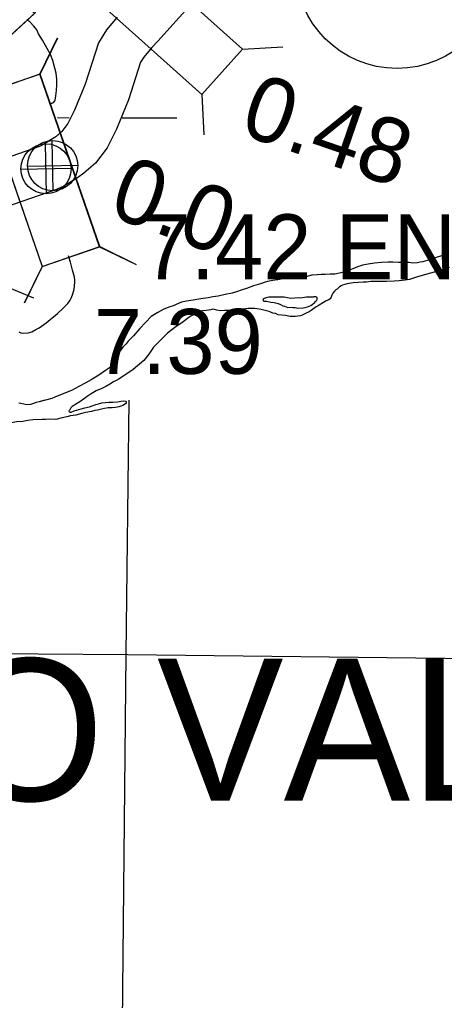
# Model space of a CAD drawing. Extents: x 369523 to 838377, y 495025 to 936819.
# Drawn here: x 596255 to 601784, y 797650 to 810419 of the extents above; entities that cross this region are included whole.
import ezdxf

# ---------------------------------------------------------------- set-up
doc = ezdxf.new("R2010")
doc.units = 0
for name, color, linetype in [('DSN_BRDG_Annotation', 7, 'Continuous'), ('DSN_DRFT_Common-Annotations', 7, 'Continuous'), ('DSN_DRFT_Common-Line', 7, 'Continuous'), ('DSN_DRFT_Junk-No-Plot', 7, 'Continuous'), ('Level 10', 7, 'Continuous'), ('Level 11', 7, 'Continuous'), ('Level 21', 7, 'Continuous'), ('Level 22', 7, 'Continuous'), ('Level 6', 7, 'Continuous')]:
    doc.layers.add(name, color=color, linetype=linetype)

msp = doc.modelspace()

# ---------------------------------------------------------------- linework, layer by layer
at = {"layer": 'DSN_DRFT_Common-Annotations'}
for p, q in [((596606, 808152), (596591, 808803)), ((596693, 808192), (596678, 808843)), ((596360, 808510), (597011, 808525)), ((596273, 808470), (596924, 808485))]:
    msp.add_line(p, q, dxfattribs=at)
for centre in [(596599, 808477), (596685, 808518)]:
    msp.add_circle(centre, 326, dxfattribs=at)
at = {"layer": 'DSN_DRFT_Common-Line'}
msp.add_circle((601167, 811103), 1320, dxfattribs=at)
at = {"layer": 'Level 10'}
for points in [[(601813, 807366), (601585, 807291), (601503, 807266), (601469, 807260), (601435, 807252), (601371, 807248), (601319, 807255), (601281, 807257), (601239, 807257), (601181, 807259), (601112, 807262), (601052, 807260), (600966, 807259), (600872, 807249), (600792, 807236), (600718, 807222), (600708, 807220)], [(600708, 807220), (600652, 807199), (600592, 807173), (600550, 807155), (600490, 807136), (600420, 807118), (600358, 807106), (600298, 807103), (600232, 807101), (600178, 807099), (600130, 807098), (600065, 807092), (600055, 807090), (599997, 807073), (599931, 807061), (599881, 807061), (599857, 807063), (599813, 807064), (599767, 807060), (599735, 807056), (599683, 807046), (599615, 807033), (599553, 807021), (599483, 807010), (599449, 807000), (599391, 806980), (599301, 806951), (599207, 806917), (599139, 806896), (599089, 806878), (599023, 806858), (598931, 806839), (598839, 806819), (598769, 806808), (598711, 806798), (598615, 806783), (598516, 806767), (598426, 806754), (598360, 806742), (598252, 806693), (598196, 806675), (598125, 806646), (598055, 806608), (597969, 806553), (597821, 806397), (597736, 806302), (597670, 806232), (597642, 806200), (597597, 806153), (597551, 806089), (597519, 806033), (597472, 805953), (597436, 805893), (597372, 805850), (597288, 805792), (597188, 805731), (597109, 805687), (597027, 805642), (596929, 805592), (596811, 805541), (596715, 805502), (596673, 805488), (596511, 805445), (596471, 805433), (596437, 805421), (596397, 805409), (596347, 805406), (596309, 805412), (596271, 805422), (596243, 805426)], [(601844, 807193), (601700, 807142), (601554, 807105), (601420, 807064), (601328, 807036), (601274, 807025), (601196, 807019), (601130, 807012), (601032, 807008), (600910, 807011), (600825, 807009), (600769, 807002), (600727, 807000), (600595, 806993), (600517, 806981), (600457, 806960), (600441, 806954), (600419, 806938), (600387, 806910), (600371, 806900), (600353, 806884), (600333, 806858), (600320, 806830), (600310, 806804), (600298, 806783), (600278, 806773), (600246, 806759), (600232, 806749), (600132, 806690), (600114, 806680), (600050, 806634), (600024, 806616), (599984, 806596), (599934, 806573), (599909, 806563), (599840, 806553), (599778, 806556), (599716, 806566), (599622, 806577), (599584, 806591), (599552, 806599), (599505, 806617), (599467, 806628), (599399, 806646), (599315, 806658)], [(599699, 806804), (599524, 806807), (599498, 806805), (599464, 806798), (599450, 806794), (599438, 806790), (599422, 806780), (599424, 806766), (599426, 806756), (599438, 806752), (599468, 806752), (599525, 806741), (599569, 806737), (599621, 806723), (599651, 806708), (599681, 806694), (599701, 806688), (599723, 806680), (599745, 806672)], [(599745, 806672), (599788, 806674), (599812, 806673), (599842, 806669), (599876, 806663), (599946, 806665), (599970, 806670), (600002, 806680), (600046, 806698), (600062, 806710), (600068, 806714), (600092, 806732), (600108, 806748), (600114, 806760), (600122, 806764), (600128, 806778), (600130, 806784), (600129, 806796), (600127, 806802), (600111, 806810), (600099, 806808), (600083, 806808), (600077, 806806), (600033, 806804), (599991, 806804), (599909, 806793), (599881, 806795), (599785, 806790), (599699, 806804)], [(599315, 806658), (599229, 806659), (599160, 806651), (599056, 806640), (598974, 806633), (598922, 806631), (598870, 806627), (598820, 806637), (598792, 806646), (598768, 806650), (598744, 806642), (598682, 806634), (598634, 806629), (598618, 806625), (598544, 806595), (598502, 806569), (598482, 806559), (598456, 806540), (598386, 806486), (598314, 806438), (598276, 806411), (598179, 806337), (598097, 806256), (597997, 806156), (597938, 806064), (597872, 805979), (597735, 805864), (597545, 805737), (597479, 805703), (597431, 805671), (597377, 805644), (597325, 805618), (597252, 805588), (597186, 805549), (597134, 805511), (597070, 805465), (597038, 805442), (596988, 805414), (596962, 805394), (596940, 805380), (596922, 805364), (596916, 805354), (596908, 805340), (596900, 805330), (596896, 805324), (596901, 805318), (596903, 805312), (596907, 805310), (596913, 805308), (596927, 805310), (596963, 805324), (597055, 805351), (597105, 805363), (597163, 805379), (597201, 805392), (597247, 805410), (597281, 805418), (597325, 805428), (597375, 805435), (597415, 805439), (597467, 805439), (597529, 805445), (597573, 805452), (597613, 805454), (597637, 805452), (597643, 805446), (597643, 805432), (597635, 805418), (597599, 805396), (597547, 805376), (597505, 805369), (597459, 805365), (597407, 805363), (597361, 805355), (597319, 805346), (597269, 805336), (597235, 805328), (597191, 805319), (597119, 805305), (597067, 805289), (596989, 805270), (596919, 805262), (596871, 805248), (596811, 805233), (596727, 805215), (596649, 805216), (596549, 805212), (596428, 805209), (596360, 805201), (596298, 805188), (596216, 805184)], [(596582, 805464), (596511, 805445), (596471, 805433), (596437, 805421), (596397, 805409), (596347, 805406), (596309, 805412), (596271, 805422), (596243, 805426)], [(596590, 805214), (596549, 805212), (596428, 805209), (596360, 805201), (596298, 805188), (596216, 805184), (596088, 805155), (595936, 805102), (595810, 805057), (595758, 805049), (595660, 805034), (595610, 805024), (595476, 805001), (595384, 804975), (595308, 804950), (595216, 804922)]]:
    msp.add_lwpolyline(points, dxfattribs=at)
at = {"layer": 'Level 11'}
for points in [[(598608, 810757), (598054, 810138), (597976, 810054), (597872, 809931), (597830, 809863), (597673, 809373), (597516, 808992), (597394, 808748), (597243, 808550), (597092, 808418), (597008, 808361), (596831, 808252), (596735, 808209), (596634, 808174)], [(597526, 810451), (597385, 810284), (597281, 810116), (597109, 809579), (596970, 809241), (596882, 809066), (596803, 808962), (596725, 808895), (596681, 808865), (596549, 808783), (596513, 808767), (596438, 808741)], [(596787, 808948), (596725, 808895), (596681, 808865), (596549, 808783), (596513, 808767), (595404, 808383), (594517, 808019)], [(596987, 808348), (596831, 808252), (596735, 808209), (595616, 807822), (594745, 807464)]]:
    msp.add_lwpolyline(points, dxfattribs=at)
at = {"layer": 'Level 21'}
for p, q in [((596518, 809709), (596749, 810183)), ((596521, 809709), (596752, 810184)), ((599154, 810036), (599681, 810065)), ((598626, 809446), (598655, 808919)), ((597295, 807463), (597770, 807232)), ((597298, 807464), (597773, 807233)), ((596547, 807204), (596316, 806729)), ((596549, 807205), (596318, 806730)), ((595951, 807000), (596438, 806796))]:
    msp.add_line(p, q, dxfattribs=at)
for points in [[(596451, 810499), (594851, 812255), (594265, 811722), (595866, 809966)], [(594278, 811733), (595878, 809977), (596464, 810511), (594863, 812266)], [(599154, 810036), (597384, 811621), (596856, 811031), (598626, 809446)], [(595770, 809450), (596547, 807204), (597295, 807463), (596518, 809709)], [(597298, 807464), (596521, 809709), (595772, 809451), (596549, 807205)]]:
    msp.add_lwpolyline(points, close=True, dxfattribs=at)
at = {"layer": 'Level 22'}
for points in [[(596899, 809138), (596749, 809139)], [(598303, 809134), (597592, 809136)], [(597454, 791662), (597589, 796921), (597640, 802158), (597679, 805464)], [(608109, 801994), (602915, 802088), (597662, 802148), (594157, 802175)]]:
    msp.add_lwpolyline(points, dxfattribs=at)
at = {"layer": 'Level 6'}
for points in [[(596649, 809329), (596663, 809330), (596673, 809330), (596689, 809336), (596697, 809340), (596713, 809360), (596718, 809370), (596726, 809428), (596734, 809496), (596741, 809574), (596739, 809642), (596730, 809722), (596714, 809788), (596687, 809887), (596655, 809967), (596614, 810043), (596555, 810150), (596503, 810236), (596478, 810286), (596442, 810334), (596387, 810389), (596350, 810418)], [(596686, 809335), (596689, 809336), (596697, 809340), (596713, 809360), (596718, 809370), (596726, 809428), (596734, 809496), (596741, 809574), (596739, 809642), (596730, 809722), (596714, 809788), (596687, 809887), (596655, 809967), (596614, 810043), (596555, 810150), (596503, 810236), (596478, 810286), (596442, 810334), (596387, 810389), (596386, 810389)], [(596247, 806353), (596273, 806343), (596303, 806335), (596365, 806340), (596415, 806356), (596467, 806386), (596509, 806407), (596599, 806471), (596654, 806513), (596696, 806548), (596750, 806594), (596816, 806656), (596882, 806725), (596911, 806767), (596927, 806793), (596945, 806835), (596961, 806893), (596963, 806905), (596974, 807003), (596976, 807031), (596968, 807067), (596943, 807157), (596916, 807261), (596890, 807343)], [(596247, 806353), (596273, 806343), (596303, 806335), (596365, 806340), (596415, 806356), (596467, 806386), (596509, 806407), (596599, 806471), (596654, 806513), (596696, 806548), (596750, 806594), (596816, 806656), (596882, 806725), (596911, 806767), (596927, 806793), (596945, 806835), (596961, 806893), (596963, 806905), (596974, 807003), (596976, 807031), (596968, 807067), (596943, 807157), (596916, 807261), (596909, 807283)]]:
    msp.add_lwpolyline(points, dxfattribs=at)

# ---------------------------------------------------------------- texts
at = {"layer": 'DSN_BRDG_Annotation'}
msp.add_text('0.0', height=844.8, rotation=340, dxfattribs=at).set_placement((597387, 807877))
msp.add_text('7.42 END', height=844.8, dxfattribs=at).set_placement((597855, 807039))
at = {"layer": 'DSN_DRFT_Common-Annotations'}
msp.add_text('CADDO VALLEY', height=1848, dxfattribs=at).set_placement((588432, 800250))
at = {"layer": 'DSN_DRFT_Junk-No-Plot'}
msp.add_text('0.48', height=844.8, rotation=341, dxfattribs=at).set_placement((599092, 808941))
msp.add_text('7.39', height=844.8, dxfattribs=at).set_placement((597222, 805807))

doc.saveas('drawing.dxf')
